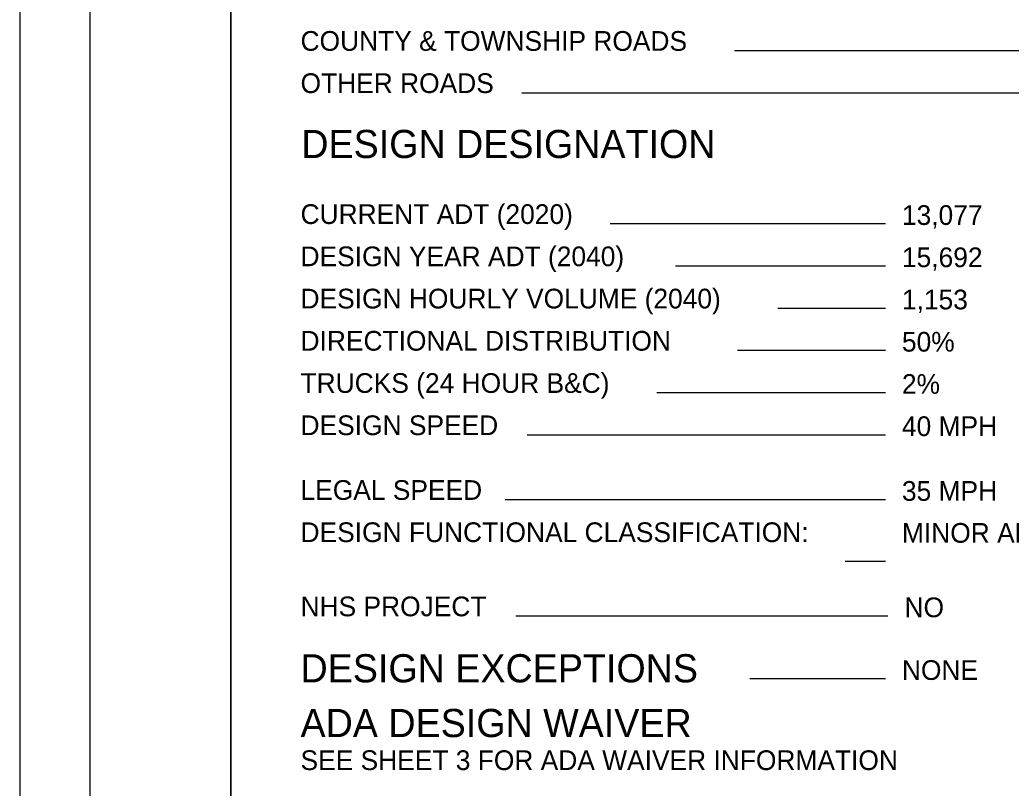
# Model space of a CAD drawing. Extents: x 0 to 69.5, y -4.5 to 22.
# Drawn here: x 0 to 7.04, y 5.46 to 10.92 of the extents above; entities that cross this region are included whole.
import ezdxf

# ---------------------------------------------------------------- set-up
doc = ezdxf.new("R2010")
doc.units = 0
doc.layers.add('SH_Border', color=7, linetype='Continuous')
doc.layers.add('SH_Data', color=7, linetype='Continuous')

msp = doc.modelspace()

# ---------------------------------------------------------------- linework, layer by layer
at = {"layer": 'SH_Border'}
for points in [[(0.5, 21.5), (1.5, 21.5), (1.5, 0.5), (0.5, 0.5)], [(1.5, 21.5), (33.5, 21.5), (33.5, 0.5), (1.5, 0.5)]]:
    msp.add_lwpolyline(points, close=True, dxfattribs=at)
at = {"layer": 'SH_Data'}
for p, q in [((7.7, 10.6975), (5.0782, 10.6975)), ((7.7, 10.3975), (3.5657, 10.3975)), ((6.1493, 9.4671), (4.1936, 9.4671)), ((6.1493, 9.1671), (4.6592, 9.1671)), ((6.1493, 8.8671), (5.3852, 8.8671)), ((6.1493, 8.5671), (5.0988, 8.5671)), ((6.1493, 8.2671), (4.5259, 8.2671)), ((6.1493, 7.9671), (3.6035, 7.9671)), ((6.1493, 7.5071), (3.4488, 7.5071)), ((6.1493, 7.0691), (5.8643, 7.0691)), ((6.1676, 6.6801), (3.5243, 6.6801)), ((6.1493, 6.2346), (5.1861, 6.2346))]:
    msp.add_line(p, q, dxfattribs=at)
msp.add_lwpolyline([(0, 0), (34, 0), (34, 22), (0, 22)], close=True, dxfattribs=at)

# ---------------------------------------------------------------- texts
for s, height, p in [('COUNTY & TOWNSHIP ROADS', 0.14, (1.9944, 10.6975)), ('OTHER ROADS', 0.14, (1.9944, 10.3975)), ('DESIGN DESIGNATION', 0.2, (2, 9.9355)), ('CURRENT ADT (2020)', 0.14, (1.9944, 9.4671)), ('13,077', 0.14, (6.267, 9.4604)), ('DESIGN YEAR ADT (2040)', 0.14, (1.9944, 9.1671)), ('15,692', 0.14, (6.267, 9.1604)), ('DESIGN HOURLY VOLUME (2040)', 0.14, (1.9944, 8.8671)), ('1,153', 0.14, (6.267, 8.8604)), ('DIRECTIONAL DISTRIBUTION', 0.14, (1.9944, 8.5671)), ('50%', 0.14, (6.267, 8.5604)), ('TRUCKS (24 HOUR B&C)', 0.14, (1.9944, 8.2671)), ('2%', 0.14, (6.267, 8.2604)), ('DESIGN SPEED', 0.14, (1.9944, 7.9671)), ('40 MPH', 0.14, (6.267, 7.9604)), ('LEGAL SPEED', 0.14, (1.9944, 7.5071)), ('35 MPH', 0.14, (6.267, 7.5004)), ('DESIGN FUNCTIONAL CLASSIFICATION:', 0.14, (1.9944, 7.2071)), ('MINOR ARTERIAL', 0.14, (6.267, 7.2025)), ('NHS PROJECT', 0.14, (1.9944, 6.6801)), ('NO', 0.14, (6.2852, 6.6735)), ('DESIGN EXCEPTIONS', 0.2, (1.9944, 6.2106)), ('NONE', 0.14, (6.267, 6.228)), ('ADA DESIGN WAIVER', 0.2, (1.9944, 5.8216)), ('SEE SHEET 3 FOR ADA WAIVER INFORMATION', 0.14, (1.9944, 5.5875))]:
    msp.add_text(s, height=height, dxfattribs=at).set_placement(p)

doc.saveas('drawing.dxf')
